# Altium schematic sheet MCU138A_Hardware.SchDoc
size 431 x 279 mm; Date: Not shown in title block; ApprovedBy: Not shown in title block; CheckedBy: Not shown in title block; Author: Not shown in title block; CompanyName: Not shown in title block; DrawnBy: Jonathan Cohen; Engineer: Not shown in title block; Organization: Not shown in title block; Address1: Not shown in title block; Address2: Not shown in title block; Address3: Not shown in title block; Address4: Not shown in title block; DocumentNumber: 3; Revision: Use project parameter SCH_Rev; SheetNumber: 2; SheetTotal: 2; PageSetup: Record=PageOptions¦CenterHorizontal=True¦CenterVertical=True¦PrintScale=1.00¦XCorrection=1.00¦YCorrection=1.00¦PrintKind=0¦BorderSize=5000000¦LeftOffset=0¦BottomOffset=0¦Orientation=2¦PaperLength=1000¦PaperWidth=1000¦Scale=100¦PaperSource=15¦PrintQuality=600¦MediaType=1¦DitherType=10¦PaperKind=Letter¦PrintScaleMode=1
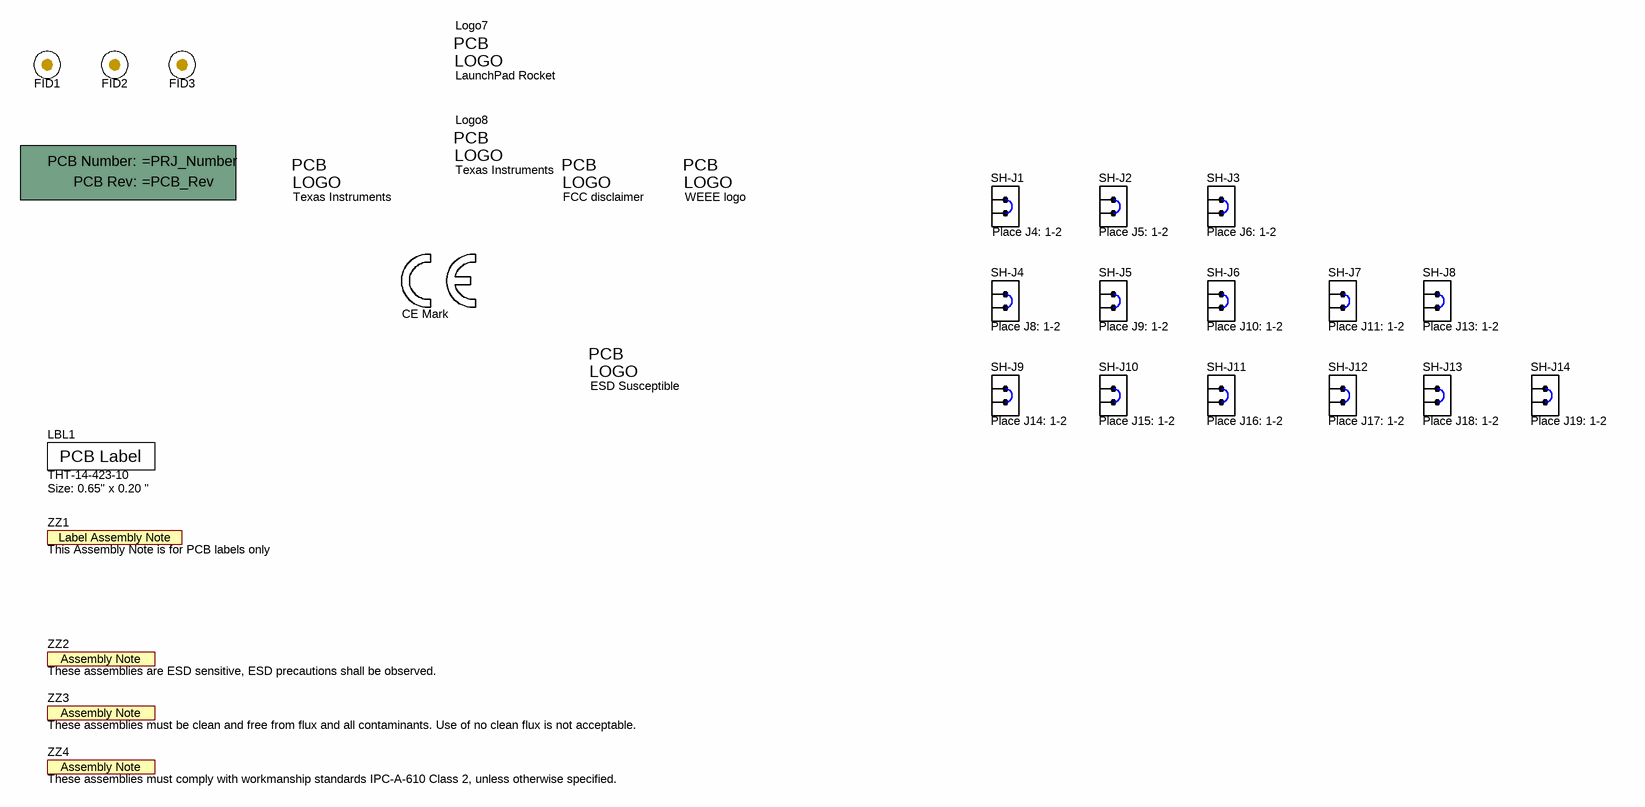
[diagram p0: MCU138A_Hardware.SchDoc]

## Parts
!PCB1  Printed Circuit Board  (value not drawn)  (mechanical)
FID1  Fiducial  [Fiducial10-20]  (value not drawn)
FID2  Fiducial  [Fiducial10-20]  (value not drawn)
FID3  Fiducial  [Fiducial10-20]  (value not drawn)
LBL1  THT-14-423-10  Note: Size: 0.65" x 0.20 "  [Label_650x200]
LOGO1  CE Mark  [CE_Mark_5mm]  (no BOM)
Logo2  Texas Instruments  [TI_Stacked_Overlay_Small]  (no BOM)
Logo3  FCC disclaimer  [FCC_disclaimer]  (no BOM)
Logo4  WEEE logo  [WEEE_Minimum]  (no BOM)
Logo5  ESD Susceptible  [ESD_Overlay_Medium]  (no BOM)
Logo7  LaunchPad Rocket  [LaunchPadRocket_Small]  (no BOM)
Logo8  Texas Instruments  [TI_Horizontal_Overlay_Medium]  (no BOM)
SH-J1  Place J4: 1-2  [SNT-100-BK-G]
SH-J2  Place J5: 1-2  [SNT-100-BK-G]
SH-J3  Place J6: 1-2  [SNT-100-BK-G]
SH-J4  Place J8: 1-2  [SNT-100-BK-G]
SH-J5  Place J9: 1-2  [SNT-100-BK-G]
SH-J6  Place J10: 1-2  [SNT-100-BK-G]
SH-J7  Place J11: 1-2  [SNT-100-BK-G]
SH-J8  Place J13: 1-2  [SNT-100-BK-G]
SH-J9  Place J14: 1-2  [SNT-100-BK-G]
SH-J10  Place J15: 1-2  [SNT-100-BK-G]
SH-J11  Place J16: 1-2  [SNT-100-BK-G]
SH-J12  Place J17: 1-2  [SNT-100-BK-G]
SH-J13  Place J18: 1-2  [SNT-100-BK-G]
SH-J14  Place J19: 1-2  [SNT-100-BK-G]
ZZ1  This Assembly Note is for PCB labels only  [AssemblyNoteLabel]  (no BOM)
ZZ2  These assemblies are ESD sensitive, ESD precautions shall be observed.  [AssemblyNote]  (no BOM)
ZZ3  These assemblies must be clean and free from flux and all contaminants. Use of no clean flux is not acceptable.  [AssemblyNote]  (no BOM)
ZZ4  These assemblies must comply with workmanship standards IPC-A-610 Class 2, unless otherwise specified.  [AssemblyNote]  (no BOM)

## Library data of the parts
!PCB1 = CMP-0003618-2: Manufacturer: Any
FID1-FID3 = CMP-0077181-1: Fiducial mark.  There is nothing to buy or mount.
LBL1 = CMP-0003625-1: Thermal Transfer Printable Labels, 0.650" W x 0.200" H - 10,000 per roll; Manufacturer: Brady; CompType: Label
LOGO1 = CMP-0074844-1: SymbolCreator: a0412235
Logo2 = CMP-0074838-1: Texas Instrument Corporate Signature; SymbolCreator: a0412235; Lib Reference: TI_Logo; Library Reference: Logo
Logo3 = CMP-0074847-1: FCC_disclaimer; Library Reference: Logo
Logo4 = CMP-0074769-1
Logo5 = CMP-0074840-1: ESD Susceptible Symbol; Library Reference: Logo; SymbolCreator: a0412235; Lib Reference: ESD_Susceptible
Logo7 = CMP-0074846-1: LaunchPad Rocket logo; Lib Reference: LaunchPad_Rocket; SymbolCreator: a0412235
Logo8 = CMP-0074838-1: Texas Instrument Corporate Signature; SymbolCreator: a0412235; Lib Reference: TI_Logo
SH-J1 = CMP-0003623-3: Shunt, 100mil, Gold plated, Black; Alternate PartNumber: 969102-0000-DA; Manufacturer: Samtec; Alternate Manufacturer: 3M; Value: 1x2; Assembly: Place J3: 2-3
SH-J2 SH-J7-SH-J14 = CMP-0003623-3: Shunt, 100mil, Gold plated, Black; Alternate PartNumber: 969102-0000-DA; Manufacturer: Samtec; Alternate Manufacturer: 3M; Value: 1x2; Assembly: Place J4: 2-3
SH-J3 = CMP-0003623-3: Shunt, 100mil, Gold plated, Black; Alternate PartNumber: 969102-0000-DA; Manufacturer: Samtec; Alternate Manufacturer: 3M; Value: 1x2; Assembly: Place J5: 2-3
SH-J4 = CMP-0003623-3: Shunt, 100mil, Gold plated, Black; Alternate PartNumber: 969102-0000-DA; Manufacturer: Samtec; Alternate Manufacturer: 3M; Value: 1x2; Assembly: Place J6: 2-3
SH-J5 SH-J6 = CMP-0003623-3: Shunt, 100mil, Gold plated, Black; Alternate PartNumber: 969102-0000-DA; Manufacturer: Samtec; Alternate Manufacturer: 3M; Value: 1x2; Assembly: Place J8: 2-3
ZZ1 = CMP-0003616-3
ZZ2 = CMP-0077236-1
ZZ3 = CMP-0077237-1
ZZ4 = CMP-0077238-1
